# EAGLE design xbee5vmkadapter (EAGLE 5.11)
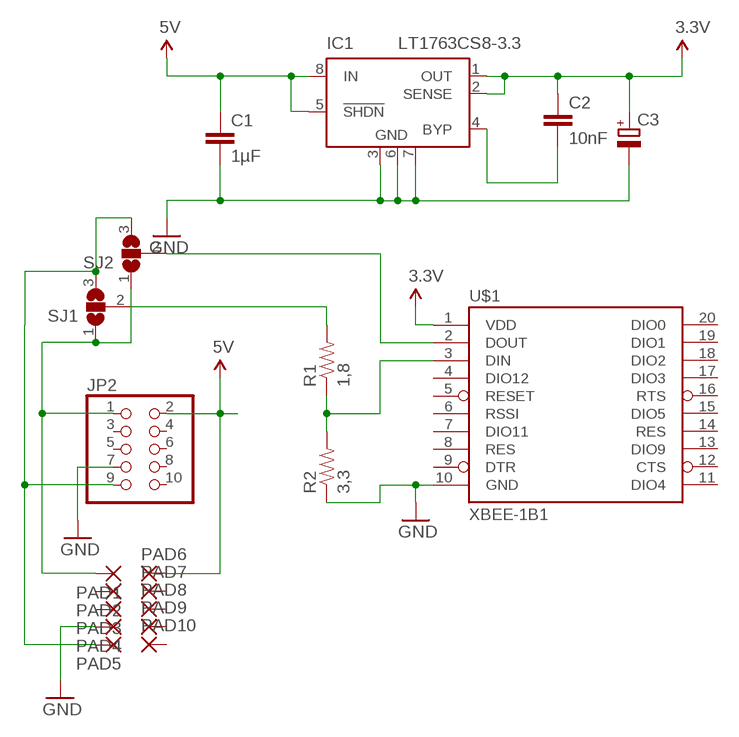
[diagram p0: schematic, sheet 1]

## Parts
C1  1µF  CAP0805  [0805]
C2  10nF  CAP0805  [0805]
C3  CPOL-EUSMCC  [SMC_C]
IC1  LT1763CS8-3.3  [SOIC8]
JP2  PINHD-2X05_2.54  [2X05]
PAD1  SMD2  [SMD1,27-2,54]
PAD2  SMD2  [SMD1,27-2,54]
PAD3  SMD2  [SMD1,27-2,54]
PAD4  SMD2  [SMD1,27-2,54]
PAD5  SMD2  [SMD1,27-2,54]
PAD6  SMD2  [SMD1,27-2,54]
PAD7  SMD2  [SMD1,27-2,54]
PAD8  SMD2  [SMD1,27-2,54]
PAD9  SMD2  [SMD1,27-2,54]
PAD10  SMD2  [SMD1,27-2,54]
R1  1,8  RESISTOR  [0805]
R2  3,3  RESISTOR  [0805]
SJ1  SJ2W  [SJ_2]
SJ2  SJ2W  [SJ_2]
U$1  XBEE-1B1  [XBEE-1]

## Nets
3.3V: C2.1 C3.+ IC1.1(OUT) IC1.2(SENSE) U$1.1(VDD)
5V: C1.1 IC1.5(!SHDN) IC1.8(IN) JP2.2 PAD6.1(P)
GND: C1.2 C3.- IC1.3(GND) IC1.6(GND) IC1.7(GND) JP2.7 PAD4.1(P) R2.1 U$1.10(GND)
N$1: R1.1 R2.2 U$1.3(DIN)
N$2: JP2.1 PAD1.1(P) SJ1.1 SJ2.1
N$3: JP2.9 PAD5.1(P) SJ1.3 SJ2.3
N$4: C2.2 IC1.4(BYP)
N$5: SJ2.2 U$1.2(DOUT)
N$8: R1.2 SJ1.2
Unconnected: JP2.3 JP2.4 JP2.5 JP2.6 JP2.8 JP2.10 PAD2.1(P) PAD3.1(P) PAD7.1(P) PAD8.1(P) PAD9.1(P) PAD10.1(P) U$1.4(DIO12) U$1.5(RESET) U$1.6(RSSI) U$1.7(DIO11) U$1.8(RES) U$1.9(DTR) U$1.11(DIO4) U$1.12(CTS) U$1.13(DIO9) U$1.14(RES) U$1.15(DIO5) U$1.16(RTS) U$1.17(DIO3) U$1.18(DIO2) U$1.19(DIO1) U$1.20(DIO0)

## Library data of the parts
C1 C2 = SparkFun:CAP: Capacitor
C3 = resistor:CPOL-EU: POLARIZED CAPACITOR, European symbol
IC1 = linear-technology:LT1763CS8: 500mA, Low Noise, LDO Micropower Regulators Source: http://cds.linear.com/docs/Datasheet/1763ff.pdf
JP2 = pinhead-2:PINHD-2X05: PIN HEADER
PAD1-PAD10 = wirepad:SMD2: SMD PAD
R1 R2 = SparkFun:RESISTOR: Resistor
SJ1 SJ2 = jumper:SJ2W: SMD solder JUMPER
U$1 = SparkFun:XBEE-1

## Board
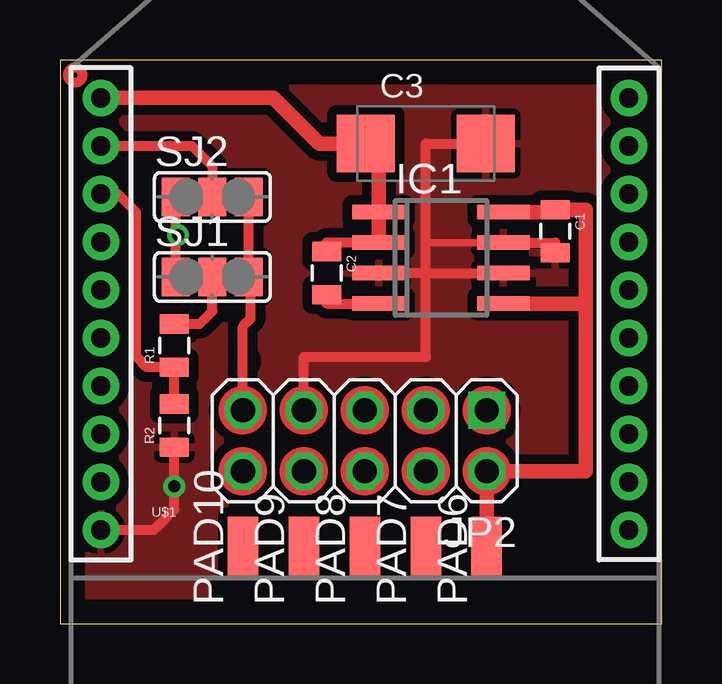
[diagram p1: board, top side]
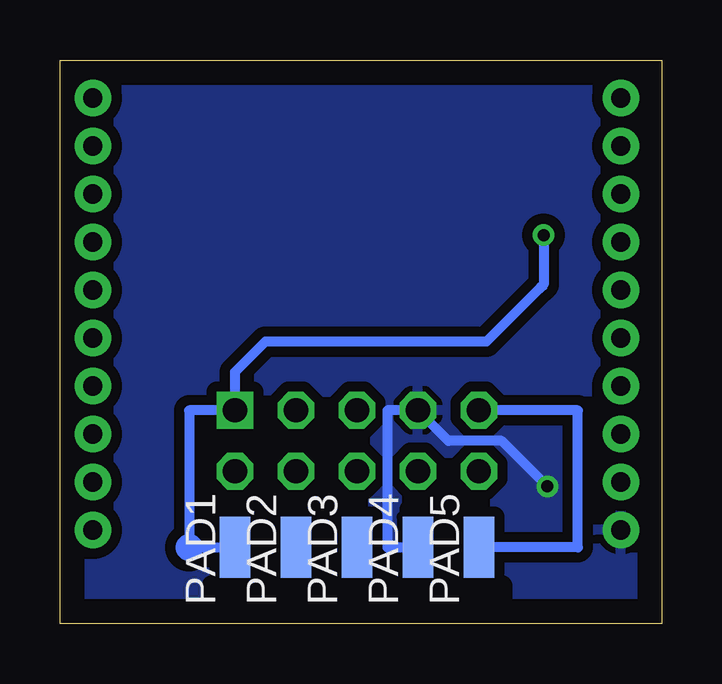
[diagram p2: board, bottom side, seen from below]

Size 25.07 x 23.49 mm. Coordinates in mm from the lower left corner, seen from the top.
Outline: 0,0 25.07,0 25.07,23.49 0,23.49 0,0
Copper layers (1*16): Top 0.035mm / dielectric 1.5mm / Bottom 0.035mm
Design rules "default": minimum track width 10mil, minimum drill 24mil, track to track 8mil, track to pad 8mil, pad to pad 8mil, via to via 8mil, smd to smd 8mil, copper to edge 40mil, drill to drill 8mil, minimum pad ring 10mil, minimum via ring 8mil, stop-mask expansion 4mil, vias tented up to drill 0mil, thermal gap 10mil
tRestrict: 6 lines
bRestrict: 6 lines

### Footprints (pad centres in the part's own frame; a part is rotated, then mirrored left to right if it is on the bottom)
0805 = smd 0.8 x 1.2: 1 -0.9,0; 2 0.9,0
SMC_C = smd 2.4 x 2.4: + -2.5,0; - 2.5,0
SOIC8 = smd 0.6 x 2.2: 1 -1.905,-2.6; 2 -0.635,-2.6; 3 0.635,-2.6; 4 1.905,-2.6; 5 1.905,2.6; 6 0.635,2.6; 7 -0.635,2.6; 8 -1.905,2.6
2X05 = drill 1.016 square: 1 -5.08,-1.27 | drill 1.016 octagon: 2 -5.08,1.27; 3 -2.54,-1.27; 4 -2.54,1.27; 5 0,-1.27; 6 0,1.27; 7 2.54,-1.27; 8 2.54,1.27; 9 5.08,-1.27; 10 5.08,1.27
SMD1,27-2,54 = smd 1.27 x 2.54: 1 0,0
SJ_2 = smd 1.168 x 1.6: 1 -1.524,0; 2 0,0; 3 1.524,0
XBEE-1 = drill 0.8 pad 1.524 round: 1 -11,20; 2 -11,18; 3 -11,16; 4 -11,14; 5 -11,12; 6 -11,10; 7 -11,8; 8 -11,6; 9 -11,4; 10 -11,2; 11 11,2; 12 11,4; 13 11,6; 14 11,8; 15 11,10; 16 11,12; 17 11,14; 18 11,16; 19 11,18; 20 11,20

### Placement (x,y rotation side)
C1  20.64,16.35 270 top
C2  11.11,14.61 270 top
C3  15.24,20 0 top
IC1  15.87,15.24 270 top
JP2  12.7,7.62 180 top
PAD1  17.78,3.18 0 bottom
PAD2  15.24,3.18 0 bottom
PAD3  12.7,3.18 0 bottom
PAD4  10.16,3.18 0 bottom
PAD5  7.62,3.18 0 bottom
PAD6  17.78,3.18 0 top
PAD7  15.24,3.18 0 top
PAD8  12.7,3.18 0 top
PAD9  10.16,3.18 0 top
PAD10  7.62,3.18 0 top
R1  4.76,11.59 90 top
R2  4.76,8.25 90 top
SJ1  6.35,14.45 0 top
SJ2  6.35,17.78 0 top
U$1  12.7,1.91 0 top

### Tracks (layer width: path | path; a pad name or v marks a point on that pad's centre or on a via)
3.3V
  Top 0.406: C3.+ 13.28,19.05 | IC1.2 11.11,15.88 C2.1 | U$1.1 1.75,21.86
  Top 0.61: 13.28,19.05 IC1.1 IC1.2 | C3.+ 10.79,20 9.21,21.59 8.89,21.9 U$1.1
5V
  Top 0.406: 17.78,13.33 IC1.5 | C1.1 20.43,17.14 | 17.78,13.33 21.91,13.33 17.78,13.33
  Top 0.61: 20.43,17.14 IC1.8 | C1.1 21.91,17.25 21.91,13.33 | 21.91,13.33 17.78,13.33 | PAD6.1 JP2.2 21.91,6.35 21.91,13.33
GND  (via drill 0.5)
  Top 0.305: 15.24,15.88 IC1.7
  Top 0.406: IC1.7 20.64,15.88 C1.2 | C3.- 15.24,20 15.24,15.88 15.24,14.61 | 15.24,14.61 IC1.6 | 15.24,14.61 IC1.3 15.24,14.61 | 15.24,14.61 15.24,11.11 11.43,11.11 | 10.16,11.11 11.43,11.11 | 10.16,11.11 11.43,11.11 | JP2.7 10.16,11.11 | U$1.10 3.9,3.9 4.13,4.13 4.76,4.76 v4.76,5.71 R2.1
  Bottom 0.406: PAD4.1 11.43,3.18 11.43,8.89 JP2.7 8.89,7.62 6.67,7.62 v4.76,5.71
  pour Bottom (isolate 0.432): 0,23.5 25.4,23.5 25.4,0 0,0
  pour Top (isolate 0.406): 0,23.5 25.4,23.5 25.4,0 0,0
N$1
  Top 0.406: U$1.3 2.41,17.9 2.86,17.46 3.18,17.14 3.18,14.92 3.18,11.11 3.6,10.69 R1.1 R2.2
N$2  (via drill 0.5)
  Top 0.406: 4.83,16.83 SJ2.1 4.83,16.83 | SJ1.1 4.83,15.88 | 4.83,15.88 4.83,16.83 | v4.92,16.19 4.83,16.1 4.83,15.88
  Bottom 0.406: PAD1.1 19.69,3.18 19.69,8.89 | JP2.1 19.69,8.89 | JP2.1 19.69,8.89 | JP2.1 17.78,10.48 16.51,11.75 7.3,11.75 5.08,13.97 4.92,14.13 v4.92,16.19
N$3
  Top 0.406: SJ2.3 SJ1.3 7.94,14.38 7.94,12.7 7.62,12.38 JP2.9 7.56,8.89
  Bottom 0.406: PAD5.1 3.49,3.18 3.49,8.89 JP2.9
N$4
  Top 0.406: C2.2 11.11,13.33 IC1.4
N$5
  Top 0.406: SJ2.2 6.35,19.05 5.71,19.68 5.49,19.9 U$1.2
N$8
  Top 0.406: R1.2 5.82,12.49 6.03,12.7 6.35,13.02 SJ1.2
(copper drawn outside any net)
  shapes: Bottom circle x1, Top circle x12

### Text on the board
bStop: Mikrokopter-Xbee | Adapter v1.1 | seb@exse.net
